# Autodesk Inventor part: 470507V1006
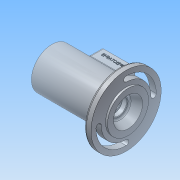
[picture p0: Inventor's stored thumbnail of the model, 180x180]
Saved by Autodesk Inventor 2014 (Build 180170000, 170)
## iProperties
Created: 2017-05
Part Number: 470507V1006
Material: 알루미늄 6061
Document SubType Name: Modeling
Designer: NET
Density: 2.71 g/cm^3
Appearance: 알루미늄 - 평지
Mass: 683.255 g
Surface Area: 619.43 cm^2
Volume: 252.123 cm^3
Author: NET
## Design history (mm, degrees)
sketch "스케치1"
  geometry: L1 (0, 0)-(0, 31); L2 (0, 31)-(102, 31); L3 (102, 31)-(102, 53); L4 (102, 53)-(112, 53); L5 (112, 53)-(112, 31); L6 (112, 31)-(115, 31); L7 (115, 31)-(115, 0); L8 (115, 0)-(0, 0); L9 (115, 22)-(102.818, 16.779); L10 (101, 14.022)-(101, 12.904); L11 (100.3, 12.5)-(94, 12.5); L12 (93.7, 12.2)-(93.7, 10); L13 (93.7, 10)-(91, 10); L14 (91, 10)-(91, 13.5); L15 (88, 16.5)-(86, 16.5); L16 (86, 16.5)-(86, 17.2); L17 (85.7, 17.5)-(74.7, 17.5); L18 (74.7, 17.5)-(74.89, 22.894); L19 (71.892, 26)-(40, 26); L20 (37, 23)-(37, 17.5); L21 (37, 17.5)-(26, 17.5); L22 (26, 17.5)-(26, 18.5); L23 (26, 18.5)-(24.25, 18.5); L24 (21, 20)-(12, 20); L25 (100.3, 12.5)-(101, 12.904); L26 (24.25, 18.5)-(24.25, 17.5); L27 (24.25, 17.5)-(21, 17.5); L28 (21, 17.5)-(21, 20); L29 (12, 20)-(12, 24); L30 (12, 24)-(9, 24); L31 (9, 24)-(9, 20); L32 (9, 20)-(0, 20); A1 r 0.3 centre (94, 12.2) between (94, 12.5) and (93.7, 12.2); A2 r 3 centre (104, 14.022) between (102.818, 16.779) and (101, 14.022); A3 r 3 centre (88, 13.5) between (91, 13.5) and (88, 16.5); A4 r 0.3 centre (85.7, 17.2) between (86, 17.2) and (85.7, 17.5); A5 r 3 centre (71.892, 23) between (74.89, 22.894) and (71.892, 26); A6 r 3 centre (40, 23) between (40, 26) and (37, 23); 4 further points
  constraints: 64 end point, 14 tangent, 12 point on circle, 8 point on line, 8 vertical, 7 horizontal, 6 centre point, 6 parallel, 2 equal radius, 1 coincident
  dimensions: "d0" = 3 distance of L5.end L6.end; "d1" = 115 distance of L1.end L6.end; "d2" = 10 distance of L3.end L4.end; "d3" = 62 diameter of L6 L8; "d4" = 62 diameter of L2 L8; "d5" = 106 diameter of L4 L8; "d6" = 44 diameter of L9.start L8; "d7" = 32 diameter of point (101, 16) L8; "d8" = 14 horizontal distance of L9.start point (101, 16); "d10" = 30 deg angle of L11 L25; "d11" = 0.7 horizontal distance of L10.end L11.start; "d12" = 0.3 radius of A1; "d13" = 7.3 horizontal distance of L12.end L10.end; "d14" = 2.7 distance of L12.end L13.end; "d15" = 25 diameter of L11 L8; "d16" = 20 diameter of L13 L8; "d17" = 3 radius of A2; "d18" = 0.3 radius of A4; "d19" = 5 horizontal distance of L13.end L15.end; "d20" = 11 distance of L17.start L17.end; "d21" = 33 diameter of L15 L8; "d22" = 35 diameter of L17 L8; "d23" = 52 diameter of L19 L8; "d24" = 38 distance of point (75, 26) point (37, 26); "d25" = 3 radius of A5; "d26" = 11 distance of L20.end L21.end; "d27" = 1.75 distance of L22.end L23.end; "d28" = 37 diameter of L23 L8; "d29" = 35 diameter of L21 L8; "d30" = 35 diameter of L27 L8; "d31" = 40 diameter of L24 L8; "d32" = 60 horizontal distance of L15.end L21.end; "d33" = 3 distance of L29.end L30.end; "d34" = 12 horizontal distance of L32.end L29.end; "d35" = 21 distance of L32.end L24.start; "d36" = 48 diameter of L30 L8
revolve "회전1" sketch "스케치1" stored, may be unused: angle "d37" = 90 deg
sketch "스케치4"
  geometry: C1 r 20 at (0, 0) reference; 3 further points
  constraints: 2 vertical alignment, 1 coincident, 1 other
node "작업 평면4"
  node "작업 평면3"
sketch "스케치5"
  geometry: L1 (-31, -20)-(-81, -20); L2 (-81, -20)-(-81, 20); L3 (-81, 20)-(-31, 20); L4 (-31, 20)-(-31, -20); L5 (-43, -11)-(-69, -11); L6 (-72, -8)-(-72, 8); L7 (-69, 11)-(-43, 11); L8 (-40, 8)-(-40, -8); L9 (0, 31)-(0, -31) reference; A1 r 3 centre (-69, 8) between (-69, 11) and (-72, 8); A2 r 3 centre (-69, -8) between (-72, -8) and (-69, -11); A3 r 3 centre (-43, 8) between (-40, 8) and (-43, 11); A4 r 3 centre (-43, -8) between (-43, -11) and (-40, -8); 10 further points
  constraints: 16 end point, 8 point on circle, 8 point on line, 8 tangent, 5 midpoint, 4 centre point, 4 horizontal, 4 vertical, 3 equal radius, 2 horizontal alignment, 1 vertical alignment
  dimensions: "d45" = 50 distance of L2.end L3.end; "d46" = 32 distance of point (-72, 11) point (-40, 11); "d47" = 40 distance of L3.end L1.start; "d48" = 22 distance of point (-40, 11) point (-40, -11); "d49" = 56 distance from line of L9 point (-56, 11); "d99" = 3 radius of A1
extrude "돌출1" join sketch "스케치5" stored distance "d50" = 10; taper "d51" = 0 deg
fillet "모깎기1" dims "d54" = 3
fillet "모깎기2" dims "d55" = 3
fillet "모깎기3" dims "d56" = 3
fillet "모깎기4" dims "d57" = 3
sketch "스케치6"
  geometry: C1 r 53 at (0, 0) reference; C2 r 31 at (0, 0) reference; A1 r 4 centre (0, 41.5) between (0, 37.5) and (0, 45.5); A2 r 4 centre (-41.5, 0) between (-45.5, 0) and (-37.5, 0); A3 r 4 centre (41.5, 0) between (45.5, 0) and (37.5, 0); A4 r 4 centre (0, -41.5) between (0, -37.5) and (0, -45.5); A5 r 37.5 centre (0, 0) between (0, 37.5) and (-37.5, 0); A6 r 37.5 centre (0, 0) between (0, -37.5) and (37.5, 0); A7 r 45.5 centre (0, 0) between (0, 45.5) and (-45.5, 0); A8 r 45.5 centre (0, 0) between (0, -45.5) and (45.5, 0)
  constraints: 16 point on circle, 8 centre point, 4 tangent, 2 horizontal alignment, 2 vertical alignment, 1 coincident, 1 concentric
  dimensions: "d61" = 45.5 radius of A7; "d62" = 37.5 radius of A5; "d63" = 37.5 radius of A6; "d64" = 45.5 radius of A8; "d65" = 4 radius of A3; "d66" = 4 radius of A4; "d67" = 4 radius of A1; "d68" = 4 radius of A2
extrude "돌출3" cut sketch "스케치6" distance "d69" = 13; taper "d70" = 0 deg
extrude "돌출4" cut sketch "스케치6" distance "d71" = 13; taper "d72" = 0 deg
hole "구멍1" diameter "d75" = 40.376; stored, may be unused: countersink angle "d79" = 90 deg, drill point angle "d81" = 118 deg; dims "d73" = 10, "d74" = 10, "d76" = 9, "d77" = 4, "d78" = 2, "d80" = 9
chamfer "모따기1" distance "d82" = 1; stored, may be unused: second distance "d83" = 2, angle "d84" = 45 deg
sketch "스케치7"
  geometry: L1 (44, 0)-(0, 0) reference; L2 (-34, -75)-(-34, -13) reference; 2 further points
  constraints: 1 other
  dimensions: "d85" = 56 distance from line of L2 point (22, -8); "d86" = 8 distance from line of point (22, -8) L1
feature "엠보싱1" sketch "스케치7" dims "d16" = 20, "d87" = 0.5, "d88" = 0
sketch "스케치8"
  geometry: L1 (34, 20)-(78, 20) reference; L2 (31, -17)-(31, 17) reference; L3 (81, 17)-(81, -17) reference; L4 (76.5, -15.5)-(35.36, -15.5); L5 (35.36, -15.5)-(35.5, 15.5); L6 (35.5, 15.5)-(76.5, 15.5); L7 (76.5, 15.5)-(76.5, -15.5); 11 further points
  constraints: 8 end point, 6 coincident, 4 midpoint, 2 horizontal, 1 horizontal alignment, 1 parallel, 1 vertical alignment
  dimensions: "d89" = 41 distance of L5.end L6.end; "d90" = 31 distance of L6.end L4.start; "d91" = 0.258944 deg angle of L3 L5
hole "구멍2" sketch "스케치8" at (76.5, -15.5), (35.36, -15.5), (35.5, 15.5), (76.5, 15.5) diameter "d92" = 2.459; stored, may be unused: countersink angle "d96" = 90 deg, drill point angle "d98" = 118 deg; dims "d93" = 6, "d94" = 4, "d95" = 2, "d97" = 8
extrude "돌출5" cut sketch "스케치5" stored distance "d100" = 13; taper "d101" = 0 deg
chamfer "모따기2" distance "d102" = 1; stored, may be unused: second distance "d103" = 2, angle "d104" = 45 deg
node "솔리드1"
node "작업 평면2"
other parameters: "d43" = -31, "d44" = 44, "d58" = 83, "d59" = 91, "d60" = 75
